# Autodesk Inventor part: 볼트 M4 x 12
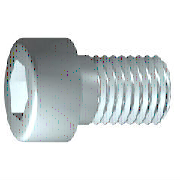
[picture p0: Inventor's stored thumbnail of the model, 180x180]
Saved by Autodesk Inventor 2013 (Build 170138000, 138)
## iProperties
IsCustomPart: 0
Created: 2012-02
Part Number: 볼트 M4 x 12
Material: 스테인리스강
Description: 6각 소켓 머리 캡 나사
Document SubType Name: Modeling
Standard: ISO 4762
Designer: mduedu
Standard Revision: Fourth edition 2004-03-01
Standards Organization: ISO
Language: ko-KR
Size Designation: M4 x 8
Categories: <MemberInstance><Categories><Category DisplayName="조임쇠" InternalName="e4da775c-781d-43d5-af7c-5136215cf5a6" Mnemonic="FSTN"><Category DisplayName="볼트" InternalN
Density: 8.08 g/cm^3
Mass: 2.29719 g
Surface Area: 3.30853 cm^2
Volume: 0.284306 cm^3
Author: mduedu
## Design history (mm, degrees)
sketch "스케치1"
  geometry: L1 (-1, 0)-(12, 0); L2 (12, 0)-(12, 2); L3 (12, 2)-(1.75, 2); L4 (1.75, 2)-(1.32, 2); L5 (1.32, 2)-(0, 2); L6 (0, 2)-(0, 3.5); L7 (0, 3.5)-(-4, 3.5); L8 (-4, 3.5)-(-4, 1.732); L9 (-4, 1.732)-(-2, 1.732); L10 (-2, 1.732)-(-1, 0); L11 (-7.2, 0)-(15.2, 0) reference; L12 (0, -0.7)-(0, 4.2) reference; L13 (1.75, 2)-(0, 2)
  constraints: 22 end point, 6 parallel, 2 collinear, 2 perpendicular, 1 horizontal, 1 point on line
  dimensions: "d1" = 10.25 distance from line of L3.end L2 (= GEL); "d2" = 0.42952 distance of L4.end L3.end (computed from GAL); "d3" = 4 distance between parallel lines of L8 L6 (= KOH); "d4" = 2 distance of L8.end L9.end (= INTI); "d5" = 60 deg angle of L10 L1; "d6" = 4 diameter of L3 L1 (= GD); "d7" = 4 diameter of L5 L1 (= BDM); "d8" = 3.4641 diameter of L9 L1 (= 1.1547 x SW); "d9" = 7 diameter of L7 L1 (= KOD); "d26" = 12 distance between parallel lines of L12 L2 (= NLG)
revolve "본체" sketch "스케치1" stored, may be unused: angle "d10" = 90 deg
sketch "스케치2"
  geometry: L1 (0, -4.9)-(0, 4.9) reference; L2 (-4.9, 0)-(4.9, 0) reference; L3 (1.732, 0)-(0.866, -1.5); L4 (0.866, -1.5)-(-0.866, -1.5); L5 (-0.866, -1.5)-(-1.732, 0); L6 (-1.732, 0)-(-0.866, 1.5); L7 (-0.866, 1.5)-(0.866, 1.5); L8 (0.866, 1.5)-(1.732, 0); 2 further points
  constraints: 12 end point, 1 coincident, 1 horizontal alignment, 1 point on line, 12 other
extrude "슬롯" join sketch "스케치2" stored distance "d11" = 10; taper "d12" = 0 deg
workplane "Work Plane1"
fillet "Fillet2" dims "d30" = 0.1 (= R)
body "Solid1"
fillet "모깎기1" dims "d17" = 0.4 (= RR)
feature "스레드" dims "d13" = 10.25 (= GEL), "d14" = 0
chamfer "모따기1" distance "d15" = 0.42941 (= -0.5 x SPD + 0.5 x GD); stored, may be unused: second distance "d16" = 0.42941 (= GUL), angle "d27" = 45 deg
other parameters: "GD" = 4 [user parameter; used in 2 equation terms], "NLG" = 12 [user parameter; used in 1 equation term], "GEL" = 10.25 [user parameter; used in 2 equation terms], "KOD" = 7 [user parameter; used in 1 equation term], "KOH" = 4 [user parameter; used in 1 equation term], "INTI" = 2 [user parameter; used in 1 equation term], "GAL" = 0.42941 (= 0.61345 x PTC) [user parameter; used in 1 equation term], "GUL" = 0.42941 (= 0.61345 x PTC) [user parameter; used in 1 equation term], "BDM" = 4 (= NND) [user parameter; used in 1 equation term], "SW" = 3 [user parameter; used in 2 equation terms], "RR" = 0.4 [user parameter; used in 1 equation term], "SPD" = 3.14117 (= NND - 1.2269 x PTC) [user parameter; used in 1 equation term], "d19" = 0, "d28" = 0, "d29" = 0, "R" = 0.1 [user parameter; used in 1 equation term], "TOA" = 30 deg [user parameter], "GD1" = 3.14117 (= THREADDIA - 1.2269 x PTC) [user parameter], "THREADDIA" = 4 [user parameter; used in 1 equation term], "FAWI" = 45 deg [user parameter], "TPU" = 14.28571 (computed from PTC) [user parameter], "PTC" = 0.7 [user parameter; used in 5 equation terms], "NND" = 4 [user parameter; used in 2 equation terms], "E0" = 3.465 (= 1.155 x SW) [user parameter]
